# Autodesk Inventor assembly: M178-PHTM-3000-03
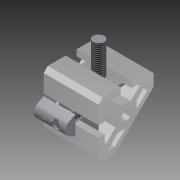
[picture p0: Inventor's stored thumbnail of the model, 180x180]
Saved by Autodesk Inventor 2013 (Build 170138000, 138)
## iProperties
Created: 2004-11
Part Number: M178-PHTM-3000-03
Document SubType Name: Assembly
Designer: Autodesk, Inc.
Manufacturer: Standard
Standards Organization: Custom
Description: PHANTOM, CORNER BRACKET 2
Mass: 127.902 g
Surface Area: 191.469 cm^2
Volume: 35.6755 cm^3
Density: 3.58514 g/cm^3
CAGE: 1LJX3
Dept. ID: Product Design
Description #2: ---
Finish #1: ---
Finish #2: ---
Material ID: ---
Project Number: ---
Author: Autodesk, Inc.
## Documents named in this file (9)
- Z:\_DATEN\Test Station\Components\21-135 Corner Phantom 2.iam
- Z:\_DATEN\Test Station\Components\21-135.ipt
- Z:\_DATEN\Test Station\Components\20-028.iam
- Z:\_DATEN\Test Station\Components\20-058.ipt
- Z:\_DATEN\Test Station\Components\20-028Z1.ipt
- Z:\_DATEN\Test Station\Components\24-125-8.ipt
- C:\Users\kelleyb.ADS\Desktop\Samples MIGRATED 2009 224 RTM_1\Standard Parts\Test Station Content\Corners, Gussets, and Mounting Plates\21-XXX Corner Elements.ipt
- C:\Users\kelleyb.ADS\Desktop\Samples MIGRATED 2009 224 RTM_1\Standard Parts\Test Station Content\Fastners\20-XXX TSlot Nuts.ipt
- C:\Users\kelleyb.ADS\Desktop\Samples MIGRATED 2009 224 RTM_1\Standard Parts\Test Station Content\Fastners\2X-YYY-ZZ IPS Screws.ipt
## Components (5 placed, 5 different names)
1. 21-135:1 — Mate:3, Mate:4, Angle:2, Mate:7, Angle:4, Mate:8, Mate:9, Angle:5
2. 20-028:2 [sub-assembly] — Mate:3, Mate:4, Angle:2, Mate:6
3. 20-058:2 — Mate:6, Mate:7, Angle:4
4. 20-028Z1:1 — Insert:1, Mate:9, Angle:5
5. 24-125-8:1 — Insert:1, Mate:8
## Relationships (10: Mate 6, Angle 3, Insert 1)
- Mate:3: 21-135:1 ↔ 20-028:2
- Mate:4: 21-135:1 ↔ 20-028:2
- Angle:2: 21-135:1 ↔ 20-028:2
- Mate:6: 20-028:2 ↔ 20-058:2
- Mate:7: 21-135:1 ↔ 20-058:2
- Angle:4: 21-135:1 ↔ 20-058:2
- Insert:1: 20-028Z1:1 ↔ 24-125-8:1
- Mate:8: 21-135:1 ↔ 24-125-8:1
- Mate:9: 21-135:1 ↔ 20-028Z1:1
- Angle:5: 21-135:1 ↔ 20-028Z1:1
